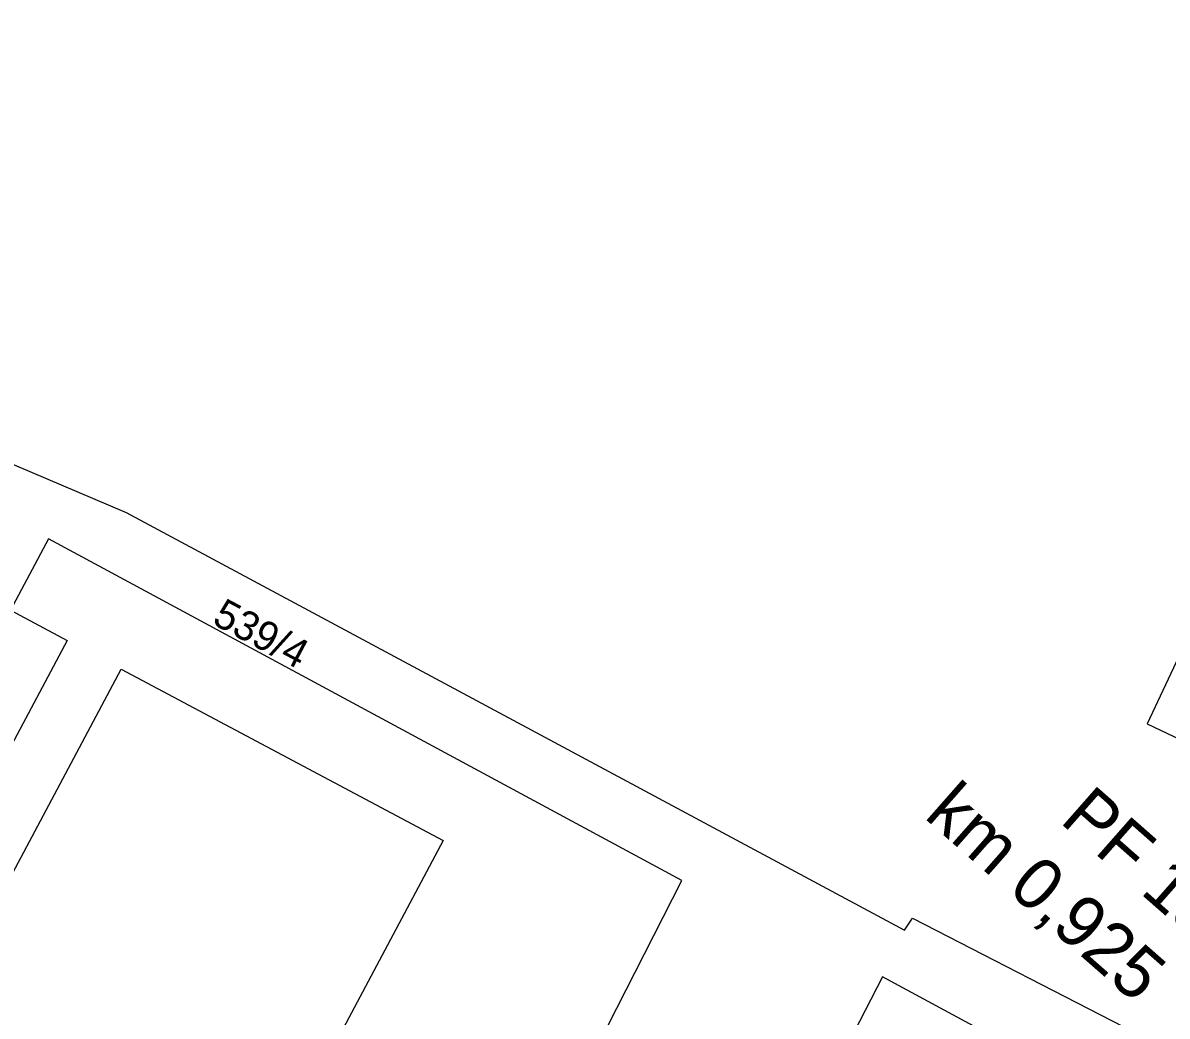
# Model space of a CAD drawing. Extents: x -555757 to -553364, y -1100723 to -1096439.
# Drawn here: x -554162.8 to -554085.1, y -1100004.2 to -1099936.8 of the extents above; entities that cross this region are included whole.
import ezdxf

# ---------------------------------------------------------------- set-up
doc = ezdxf.new("R2010")
doc.units = 0
for name, color, linetype in [('00_NÁVRH - 0.35 mm', 7, 'Continuous'), ('00_NÁVRH - Řezy', 7, 'Continuous'), ('C$SLO$PARCELY', 7, 'Continuous'), ('HRANICE$PARCELY', 7, 'Continuous')]:
    doc.layers.add(name, color=color, linetype=linetype)

msp = doc.modelspace()

# ---------------------------------------------------------------- linework, layer by layer
at = {"layer": '00_NÁVRH - 0.35 mm'}
for points in [[(-554121.038, -1100084.071), (-554120.29, -1100083.214), (-554115.883, -1100078.111), (-554102.603, -1100063.374), (-554102.321, -1100063.071), (-554101.974, -1100062.568), (-554098.629, -1100057.629), (-554090.824, -1100045.893), (-554079.91, -1100029.638), (-554073.105, -1100020.173), (-554070.185, -1100015.869), (-554068.794, -1100013.879), (-554068.294, -1100013.108), (-554068.132, -1100012.935), (-554066.204, -1100011.19), (-554064.267, -1100009.642), (-554063.994, -1100009.367), (-554063.697, -1100008.997), (-554060.622, -1100005.511), (-554059.621, -1100003.783), (-554050.789, -1099987.466), (-554049.862, -1099985.778), (-554049.243, -1099984.937), (-554048.427, -1099983.926), (-554045.767, -1099980.137), (-554042.801, -1099975.907), (-554027.312, -1099951.702), (-554020.539, -1099939.972), (-554013.16, -1099925.654), (-554007.549, -1099916.144), (-554003.454, -1099909.132), (-553999.358, -1099902.06), (-553990.092, -1099886.703), (-553982.385, -1099870.689), (-553980.731, -1099867.786), (-553977.585, -1099863.551), (-553962.516, -1099845.337), (-553947.814, -1099825.687), (-553946.507, -1099824.029), (-553944.906, -1099822.501), (-553939.459, -1099817.055), (-553931.477, -1099809.073), (-553930.86, -1099808.418), (-554120.665, -1100083.642), (-553931.168, -1099808.746)], [(-554124.193, -1100083.594), (-554124.119, -1100083.516), (-554110.805, -1100070.231), (-554105.198, -1100064.482), (-554103.49, -1100062.566), (-554101.126, -1100059.001), (-554090.445, -1100041.882), (-554078.828, -1100024.562), (-554074.733, -1100018.755), (-554072.698, -1100015.754), (-554070.371, -1100012.492), (-554069.368, -1100011.504), (-554067.52, -1100009.973), (-554065.694, -1100008.489), (-554065.313, -1100008.125), (-554064.49, -1100007.088), (-554062.354, -1100004.152), (-554061.804, -1100003.347), (-554060.852, -1100001.711), (-554052.165, -1099985.111), (-554051.812, -1099984.494), (-554050.669, -1099982.712), (-554043.661, -1099972.166), (-554034.822, -1099959.127), (-554029.076, -1099950.629), (-554025.145, -1099944.316), (-554022.035, -1099939.064), (-554014.682, -1099924.703), (-554011.646, -1099919.555), (-554006.099, -1099910.009), (-554000.807, -1099901.064), (-553993.235, -1099884.567), (-553982.687, -1099867.168), (-553982.282, -1099866.584), (-553982.022, -1099866.223), (-553964.16, -1099843.951), (-553948.401, -1099823.649), (-553947.524, -1099822.579), (-553946.714, -1099821.802), (-553939.485, -1099815.185), (-553931.375, -1099807.503), (-554124.156, -1100083.555), (-553935.412, -1099811.363)]]:
    msp.add_open_spline(points, degree=3, dxfattribs=at)
at = {"layer": 'HRANICE$PARCELY'}
msp.add_line((-554161.03, -1099971.81), (-554163.62, -1099976.67), dxfattribs=at)
for points in [[(-554198.22, -1099951.97), (-554155.76, -1099970.04), (-554102.94, -1099998.39), (-554102.39, -1099997.57), (-554087.26, -1100005.36), (-554089.31, -1100009.35), (-554090.64, -1100009.01)], [(-554119.28, -1100030.39), (-554132.57, -1100023.55), (-554118.06, -1099995.02), (-554161.03, -1099971.81)], [(-554163.62, -1099976.67), (-554159.77, -1099978.72), (-554182.41, -1100021.27), (-554204.17, -1100009.69), (-554194.52, -1099991.55)], [(-554081.09, -1099980.45), (-554083.97, -1099979.08), (-554086.46, -1099984.38), (-554069.69, -1099992.35), (-554068.56, -1099989.96), (-554067.88, -1099990.28), (-554063.74, -1099992.25), (-554062.42, -1099989.46), (-554066.56, -1099987.49), (-554067.24, -1099987.17), (-554067.17, -1099987.04), (-554074.69, -1099983.48)], [(-554134.24, -1099992.31), (-554156.88, -1100034.86), (-554178.75, -1100023.22), (-554156.1, -1099980.67), (-554134.24, -1099992.31)], [(-554090.64, -1100009.01), (-554104.44, -1100001.56), (-554119.28, -1100030.39)]]:
    msp.add_lwpolyline(points, dxfattribs=at)

# ---------------------------------------------------------------- texts
at = {"layer": '00_NÁVRH - Řezy'}
for s, p in [('km 0,925', (-554101.678, -1099990.721)), ('PF 15', (-554092.474, -1099991.031))]:
    msp.add_text(s, height=3.5, rotation=318.66085, dxfattribs=at).set_placement(p)
at = {"layer": 'C$SLO$PARCELY'}
msp.add_text('539/4', height=2, rotation=332, dxfattribs=at).set_placement((-554150.013, -1099977.555))

doc.saveas('drawing.dxf')
